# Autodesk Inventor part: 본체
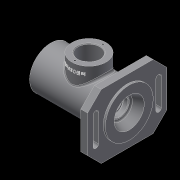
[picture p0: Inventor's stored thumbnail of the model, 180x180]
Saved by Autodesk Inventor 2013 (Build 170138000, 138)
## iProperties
Created: 2017-10
Part Number: 본체
Material: 일반
Document SubType Name: Modeling
Designer: Administrator
Density: 1 g/cm^3
Mass: 272.372 g
Surface Area: 650.981 cm^2
Volume: 272.372 cm^3
Author: Administrator
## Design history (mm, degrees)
sketch "스케치1"
  geometry: L1 (-115, 0)-(0, 0); L2 (-115, 21)-(-106, 21); L3 (-106, 21)-(-106, 24); L4 (-106, 24)-(-103, 24); L5 (-103, 24)-(-103, 20); L6 (-103, 20)-(-94, 20); L7 (-94, 20)-(-94, 17.5); L8 (-94, 17.5)-(-90.75, 17.5); L9 (-90.75, 17.5)-(-90.75, 18.5); L10 (-90.75, 18.5)-(-89, 18.5); L11 (-89, 18.5)-(-89, 17.5); L12 (-89, 17.5)-(-78, 17.5); L13 (-78, 17.5)-(-78, 26); L14 (-78, 26)-(-40, 26); L15 (-40, 26)-(-40, 17.5); L16 (-40, 17.5)-(-29, 17.5); L17 (-29, 17.5)-(-29, 16.5); L18 (-29, 16.5)-(-24, 16.5); L19 (-24, 16.5)-(-24, 10); L20 (-24, 10)-(-21.3, 10); L21 (0, 22)-(0, 35); L22 (0, 35)-(-13, 35); L23 (-13, 35)-(-13, 31); L24 (-13, 31)-(-115, 31); L25 (-115, 31)-(-115, 21); L26 (-21.3, 10)-(-21.3, 12.5); L27 (-21.3, 12.5)-(-14, 12.5); L28 (-14, 12.5)-(-14, 16); L29 (-14, 16)-(0, 22); 1 further point
  constraints: 58 end point, 22 parallel, 5 perpendicular, 2 collinear, 2 vertical alignment, 1 coincident, 1 horizontal
  dimensions: "d0" = 115 distance of L1.start L1.end; "d2" = 42 diameter of L2 L1; "d3" = 48 diameter of L4 L1; "d4" = 40 diameter of L6 L1; "d5" = 35 diameter of L8 L1; "d6" = 37 diameter of L10 L1; "d7" = 1.75 distance between parallel lines of L11 L9; "d8" = 52 diameter of L14 L1; "d9" = 33 diameter of L18 L1; "d10" = 20 diameter of L20 L1; "d11" = 25 diameter of L27 L1; "d12" = 32 diameter of L28.end L1; "d13" = 44 diameter of L21.start L1; "d14" = 70 diameter of L22 L1; "d15" = 62 diameter of L24 L1; "d16" = 12 distance between parallel lines of L5 L25; "d17" = 3 distance between parallel lines of L5 L3; "d18" = 21 distance between parallel lines of L7 L25; "d19" = 26 distance between parallel lines of L11 L25; "d20" = 11 distance between parallel lines of L13 L11; "d21" = 11 distance between parallel lines of L17 L15; "d22" = 14 distance between parallel lines of L28 L21; "d23" = 60 distance between parallel lines of L17 L11; "d24" = 5 distance between parallel lines of L19 L17; "d25" = 2.7 distance between parallel lines of L26 L19; "d26" = 13 distance between parallel lines of L23 L21
revolve "회전1" sketch "스케치1" stored, may be unused: angle "d27" = 90 deg
node "작업 평면2"
sketch "스케치2"
  geometry: L1 (115, 31)-(115, -31) reference; C1 r 25 at (59, 0); 1 further point
  constraints: 1 centre point, 1 horizontal alignment
  dimensions: "d31" = 56 distance from line of C1.centre L1; "d34" = 50 diameter of C1
extrude "돌출1" join sketch "스케치2" stored distance "d32" = 10; taper "d33" = 0 deg
sketch "스케치3"
  geometry: C1 r 25 at (0, 0) reference; 1 further point
hole "구멍1" sketch "스케치3" at (0, 0) diameter "d35" = 32; stored, may be unused: countersink angle "d39" = 90 deg, drill point angle "d41" = 118 deg; dims "d36" = 6, "d37" = 4, "d38" = 2, "d40" = 47
node "작업 평면3"
sketch "스케치4"
  geometry: L1 (-58, 47)-(58, 47); L2 (58, 47)-(58, -47); L3 (58, -47)-(-58, -47); L4 (-58, -47)-(-58, 47); L5 (-58, -47)-(58, 47); C1 r 35 at (0, 0) reference; 2 further points
  constraints: 10 end point, 2 parallel, 1 coincident, 1 horizontal, 1 midpoint, 1 perpendicular
  dimensions: "d43" = 94 distance of L1.end L2.end; "d45" = 116 distance of L2.end L3.end
extrude "돌출2" join sketch "스케치4" distance "d46" = 10; taper "d47" = 0 deg
chamfer "모따기1" distance "d48" = 20; stored, may be unused: second distance "d49" = 2, angle "d50" = 45 deg
sketch "스케치5"
  geometry: L1 (-50, -20)-(-50, 20); L2 (-42, 20)-(-42, -20); A1 r 4 centre (-46, 20) between (-42, 20) and (-50, 20); A2 r 4 centre (-46, -20) between (-50, -20) and (-42, -20); 2 further points
  constraints: 4 end point, 4 point on circle, 4 tangent, 2 centre point, 1 horizontal alignment, 1 midpoint, 1 parallel, 1 vertical
  dimensions: "d51" = 46 horizontal distance of A2.centre point (0, 0); "d52" = 40 distance of A2.centre A1.centre; "d54" = 4 radius of A1
extrude "돌출3" cut sketch "스케치5" stored distance "d55" = 10; taper "d56" = 0 deg
sketch "스케치6" dims "d57" = 41
  geometry: C1 r 25 at (0, 0) reference; 3 further points
  constraints: 2 vertical alignment, 1 coincident, 2 other
hole "구멍2" sketch "스케치6" at (0, 20.5) diameter "d59" = 2.459; stored, may be unused: countersink angle "d63" = 90 deg, drill point angle "d65" = 118 deg; dims "d60" = 6, "d61" = 4, "d62" = 2, "d64" = 8
node "작업 평면4"
sketch "스케치7"
  geometry: L1 (-56, -78)-(-56, -16) reference; L2 (-25, 0)-(25, 0) reference; 2 further points
  constraints: 1 other
  dimensions: "d69" = 56 distance from line of point (0, -10) L1; "d70" = 10 distance from line of L2 point (0, -10)
feature "엠보싱1" sketch "스케치7" dims "d8" = 52, "d71" = 0.5, "d72" = 0
feature "스레드1" dims "d73" = 10, "d74" = 0
chamfer "모따기2" distance "d75" = 1; stored, may be unused: second distance "d76" = 2, angle "d77" = 45 deg
fillet "모깎기1" dims "d78" = 3
fillet "모깎기2" dims "d79" = 0.3, "d80" = 3
chamfer "모따기3" distance "d81" = 0.7; stored, may be unused: second distance "d82" = 2, angle "d83" = 30 deg
fillet "모깎기3" dims "d88" = 3
node "솔리드1"
mirror "대칭1"
pattern_circular "원형 패턴1" dims angle "d67" = 360 deg
other parameters: "d28" = 47, "d42" = -3, "d84" = 0.5, "d85" = 2, "d86" = 0
